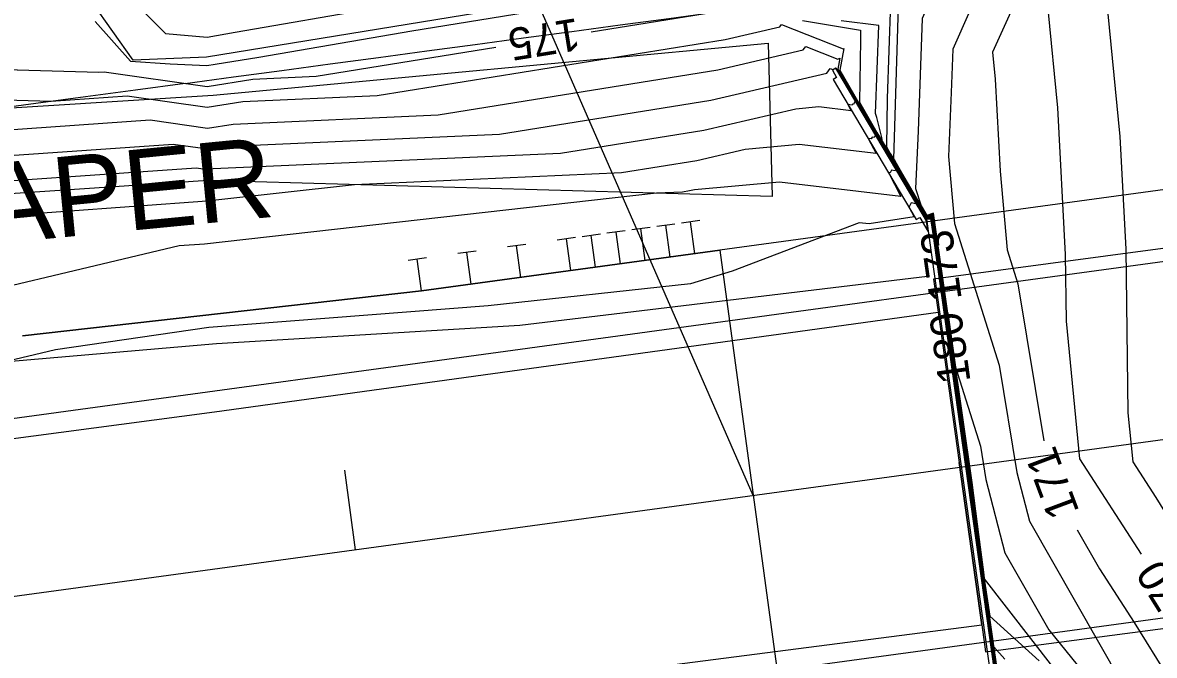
# Model space of a CAD drawing. Extents: x 2086416 to 2115205, y 575507 to 632762.
# Drawn here: x 2111995.5 to 2112066, y 581711.6 to 581751.1 of the extents above; entities that cross this region are included whole.
import ezdxf

# ---------------------------------------------------------------- set-up
doc = ezdxf.new("R2010")
doc.units = 0
for name, color, linetype in [('Default', 7, 'Continuous'), ('DTM Contours Major', 7, 'Continuous'), ('DTM Contours Major Text', 7, 'Continuous'), ('DTM Contours Minor', 7, 'Continuous'), ('DTM Contours Minor Text', 7, 'Continuous'), ('Exist Guardrail', 7, 'Continuous'), ('Exist Hydro Stream or Body of Water', 7, 'Continuous'), ('Exist Right of Way Line', 7, 'Continuous'), ('Exist Roads EOP', 7, 'Continuous'), ('Exist Structure Major Bridge WW', 7, 'Continuous'), ('Exist Structure Major Deck Tunnel Box Culvert', 7, 'Continuous'), ('Exist Vegetation Woods Line', 7, 'Continuous'), ('Prop Horizontal Alignment', 7, 'Continuous'), ('Prop Horizontal Alignment Station Label', 7, 'Continuous'), ('Prop Horizontal Alignment Tick Small', 7, 'Continuous'), ('Prop Roadway Bridge', 7, 'Continuous'), ('Prop SS Cut Line', 7, 'Continuous')]:
    doc.layers.add(name, color=color, linetype=linetype)

msp = doc.modelspace()

# ---------------------------------------------------------------- linework, layer by layer
at = {"layer": 'Default'}
for p, q in [((2111430.061, 581649.328), (2112312.029, 581769.688)), ((2111433.036, 581627.53), (2112315.004, 581747.89)), ((2112036.158, 581738.516), (2112035.023, 581738.361)), ((2112035.861, 581736.457), (2112035.591, 581738.439)), ((2112037.706, 581738.728), (2112036.571, 581738.573)), ((2112037.409, 581736.669), (2112037.139, 581738.65)), ((2112031.514, 581737.882), (2112030.379, 581737.728)), ((2112031.217, 581735.823), (2112030.946, 581737.805)), ((2112033.062, 581738.094), (2112031.927, 581737.939)), ((2112032.765, 581736.035), (2112032.494, 581738.016)), ((2112034.61, 581738.305), (2112033.475, 581738.15)), ((2112034.313, 581736.246), (2112034.042, 581738.228)), ((2112026.869, 581737.249), (2112025.734, 581737.094)), ((2112026.572, 581735.19), (2112026.302, 581737.171)), ((2112029.966, 581737.671), (2112028.831, 581737.516)), ((2112029.668, 581735.612), (2112029.398, 581737.594)), ((2112020.677, 581736.404), (2112019.542, 581736.249)), ((2112020.38, 581734.345), (2112020.109, 581736.326)), ((2112038.957, 581736.88), (2112020.38, 581734.345)), ((2112020.38, 581734.345), (2112038.957, 581736.88)), ((2112023.773, 581736.826), (2112022.638, 581736.671)), ((2112023.476, 581734.767), (2112023.205, 581736.749)), ((2111995.53, 581731.542), (2112020.38, 581734.345)), ((2112020.38, 581734.345), (2111995.53, 581731.542))]:
    msp.add_line(p, q, dxfattribs=at)
at = {"layer": 'DTM Contours Major'}
for points in [[(2112093.804, 581744.757), (2112090.042, 581754.014), (2112084.44, 581764.888), (2112082.003, 581767.922), (2112071.785, 581774.964), (2112068.207, 581770.089), (2112066.687, 581768.005), (2112059.39, 581751.908), (2112059.991, 581745.748), (2112060.467, 581736.615), (2112060.524, 581732.474), (2112061.368, 581723.884), (2112065.2, 581717.945)], [(2112030.936, 581750.481), (2112039.721, 581751.9)], [(2112044.102, 581751.189), (2112047.713, 581750.589), (2112047.719, 581749.965), (2112047.666, 581746.104), (2112048.736, 581744.226), (2112050.093, 581742.006), (2112051.838, 581738.979), (2112051.843, 581739), (2112051.898, 581739.008), (2112052.22, 581739.112), (2112054.232, 581725.192), (2112054.991, 581719.398), (2112055.55, 581715.417), (2112056.626, 581707.916)], [(2111925.764, 581740.81), (2111939.964, 581741.818), (2111942.786, 581742.121), (2111957.222, 581743.139), (2111973.757, 581745.604), (2111976.305, 581745.781), (2111990.111, 581748.256), (2112000.275, 581747.973), (2112000.618, 581747.997), (2112007.016, 581747.085), (2112009.871, 581747.542), (2112013.821, 581747.717), (2112025.013, 581749.525)], [(2112052.875, 581733.796), (2112052.825, 581734.177), (2112052.137, 581738.939), (2112052.027, 581738.903), (2112051.845, 581738.878), (2112051.827, 581738.808), (2112051.245, 581739.819), (2112048.65, 581744.064), (2112048.579, 581743.898), (2112048.439, 581743.929), (2112048.382, 581743.814), (2112048.199, 581743.844), (2112048.686, 581742.903), (2112043.902, 581743.464), (2112040.534, 581743.16), (2112037.519, 581742.461), (2112032.824, 581741.703), (2112016.209, 581740.966), (2112007.008, 581739.932), (2111993.349, 581738.951), (2111987.178, 581737.484), (2111979.955, 581737.182), (2111962.616, 581735.882)], [(2111984.298, 581691.845), (2111991.51, 581693.189), (2111995.196, 581693.902), (2112011.564, 581696.953), (2112016.807, 581698.169), (2112041.287, 581700.92), (2112041.717, 581701.015), (2112046.837, 581701.591), (2112048.852, 581702.413), (2112054.344, 581703.379), (2112054.34, 581703.36), (2112054.13, 581701.681), (2112054.225, 581701.662), (2112054.385, 581701.619), (2112055.986, 581706.942), (2112056.231, 581707.78), (2112056.23, 581707.966), (2112056.399, 581707.991), (2112056.489, 581708.003), (2112056.386, 581708.74), (2112056.033, 581711.197), (2112053.695, 581727.852)]]:
    msp.add_lwpolyline(points, dxfattribs=at)
at = {"layer": 'DTM Contours Minor'}
for points in [[(2112088.832, 581814.717), (2112079.117, 581800.733), (2112078.139, 581799.131), (2112071.052, 581784.529), (2112066.895, 581774.978), (2112066.081, 581772.081), (2112065.416, 581771.202), (2112065.876, 581771.198), (2112064.244, 581767.513), (2112055.948, 581749.212), (2112056.111, 581747.536), (2112056.41, 581741.807), (2112056.854, 581736.905), (2112057.524, 581734.784), (2112059.14, 581725.01)], [(2112066.275, 581795.739), (2112047.998, 581793.548), (2112061.063, 581775.542), (2112061.722, 581774.652), (2112054.081, 581764.549), (2112060.152, 581764.507), (2112053.463, 581749.403), (2112053.368, 581746.704), (2112053.198, 581742.712), (2112053.575, 581738.546), (2112056.358, 581729.732), (2112057.466, 581723.036), (2112058.244, 581720.01), (2112063.976, 581709.948), (2112064.076, 581709.792), (2112064.176, 581709.631), (2112064.52, 581708.577), (2112068.431, 581698.956)], [(2111990.873, 581783.424), (2111997.45, 581781.941), (2111996.551, 581772.464), (2111996.221, 581769.419), (2112001.249, 581756.244), (2112002.407, 581752.402), (2112004.434, 581750.394), (2112007.018, 581750.164), (2112008.767, 581750.469), (2112026.584, 581753.57), (2112026.238, 581757.953), (2112041.947, 581766.094), (2112043.662, 581758.151), (2112045.558, 581757.878), (2112054.428, 581757.817), (2112051.55, 581751.319), (2112051.304, 581744.309), (2112051.151, 581740.719), (2112051.49, 581739.658), (2112051.842, 581739.048), (2112051.842, 581739.049), (2112051.846, 581739.05), (2112052.253, 581739.181), (2112052.291, 581738.921)], [(2112090.836, 581746.669), (2112087.884, 581753.931), (2112083.489, 581762.461), (2112080.052, 581766.74), (2112072.781, 581771.751), (2112070.235, 581768.282), (2112067.06, 581763.928), (2112062.833, 581754.603), (2112063.87, 581743.961), (2112064.236, 581736.951), (2112064.376, 581726.748), (2112064.675, 581723.707), (2112066.115, 581721.476), (2112068.073, 581718.32), (2112071.422, 581714.164), (2112071.682, 581713.878)], [(2112000.048, 581751.131), (2112002.239, 581748.66), (2112004.722, 581748.487), (2112006.997, 581748.388), (2112007.528, 581748.479), (2112010.249, 581748.915), (2112019.764, 581750.541), (2112039.664, 581753.78)], [(2112049.596, 581752.312), (2112049.386, 581746.335), (2112049.345, 581743.317), (2112049.573, 581742.917), (2112049.862, 581742.443), (2112051.84, 581739.014), (2112051.842, 581739.025), (2112051.872, 581739.029), (2112052.236, 581739.147), (2112054.513, 581723.395), (2112055.372, 581716.839), (2112055.453, 581716.261), (2112055.766, 581714.082), (2112058.851, 581711.313)], [(2111989.42, 581746.388), (2111997.31, 581746.168), (2112002.05, 581746.498), (2112007.032, 581745.788), (2112009.255, 581746.143), (2112017.621, 581746.514), (2112039.28, 581750.013), (2112042.69, 581750.803), (2112042.793, 581750.943), (2112046.635, 581749.422), (2112046.673, 581749.442), (2112046.438, 581748.1), (2112047.898, 581745.536), (2112050.323, 581741.569), (2112051.835, 581738.945), (2112051.843, 581738.976), (2112051.923, 581738.987), (2112052.203, 581739.077), (2112053.951, 581726.989), (2112054.61, 581721.958), (2112055.647, 581714.573), (2112056.578, 581708.081)], [(2111994.345, 581744.364), (2112003.483, 581744.998), (2112007.047, 581744.49), (2112008.638, 581744.744), (2112021.422, 581745.311), (2112038.84, 581748.125), (2112044.156, 581749.357), (2112044.316, 581749.575), (2112046.314, 581748.784), (2112046.434, 581748.846), (2112046.313, 581748.159), (2112047.061, 581746.845), (2112050.553, 581741.131), (2112051.833, 581738.911), (2112051.844, 581738.951), (2112051.949, 581738.966), (2112052.187, 581739.043), (2112053.669, 581728.786), (2112054.229, 581724.517), (2112055.743, 581713.729), (2112056.53, 581708.246)], [(2111991.38, 581742.559), (2112004.916, 581743.499), (2112007.063, 581743.193), (2112008.021, 581743.346), (2112025.223, 581744.108), (2112038.399, 581746.237), (2112045.621, 581747.911), (2112045.839, 581748.207), (2112045.994, 581748.146), (2112046.194, 581748.25), (2112046.188, 581748.217), (2112046.224, 581748.155), (2112050.784, 581740.694), (2112051.831, 581738.876), (2112051.844, 581738.927), (2112051.975, 581738.945), (2112052.17, 581739.008), (2112053.388, 581730.583), (2112053.847, 581727.076), (2112055.84, 581712.885), (2112056.482, 581708.41)], [(2112056.434, 581708.575), (2112055.937, 581712.041), (2112053.466, 581729.636), (2112053.107, 581732.38), (2112052.154, 581738.974), (2112052.001, 581738.924), (2112051.845, 581738.902), (2112051.829, 581738.842), (2112051.014, 581740.256), (2112047.384, 581746.196), (2112047.286, 581745.963), (2112047.223, 581745.977), (2112047.197, 581745.925), (2112046.937, 581745.968), (2112047.143, 581745.571), (2112045.122, 581745.808), (2112043.698, 581745.679), (2112037.959, 581744.349), (2112029.023, 581742.905), (2112007.404, 581741.947), (2112007.078, 581741.895), (2112006.348, 581741.999), (2111988.896, 581740.788)], [(2112056.13, 581710.354), (2112052.704, 581734.754), (2112052.544, 581735.974), (2112052.121, 581738.904), (2112052.053, 581738.882), (2112051.845, 581738.853), (2112051.825, 581738.774), (2112051.475, 581739.381), (2112049.915, 581741.933), (2112049.873, 581741.834), (2112049.655, 581741.881), (2112049.566, 581741.702), (2112049.461, 581741.72), (2112050.228, 581740.236), (2112042.683, 581741.121), (2112037.37, 581740.641), (2112037.078, 581740.573), (2112036.624, 581740.5), (2112035.018, 581740.429), (2112006.848, 581737.262), (2112005.287, 581737.15), (2111987.473, 581732.914)], [(2112056.227, 581709.51), (2112052.323, 581737.313), (2112052.263, 581737.771), (2112052.104, 581738.87), (2112052.078, 581738.862), (2112051.846, 581738.829), (2112051.823, 581738.739), (2112051.705, 581738.944), (2112051.18, 581739.802), (2112051.166, 581739.769), (2112050.871, 581739.833), (2112050.751, 581739.591), (2112050.722, 581739.595), (2112051.052, 581738.959), (2112048.264, 581738.519), (2112047.644, 581738.592), (2112039.718, 581735.589), (2112037.125, 581734.798), (2112024.517, 581733.414), (2112007.137, 581732.061), (2111997.584, 581730.679), (2111987.768, 581728.345)], [(2112053.149, 581732.983), (2112053.637, 581729.605), (2112055.192, 581724.68), (2112055.536, 581722.602), (2112056.71, 581718.039), (2112059.448, 581713.234), (2112063.337, 581708.445), (2112065.522, 581703.069), (2112063.58, 581699.407), (2112062.948, 581692.044), (2112060.031, 581679.765), (2112054.922, 581680.384), (2112054.842, 581673.735)], [(2112061.214, 581719.459), (2112062.599, 581717.028), (2112064.756, 581713.686), (2112066.895, 581710.238), (2112070.142, 581700.284), (2112072.84, 581697.236), (2112070.631, 581692.11), (2112066.05, 581673.082), (2112062.824, 581653.079), (2112059.859, 581649.8), (2112053.487, 581643.439), (2112049.372, 581635.991)]]:
    msp.add_lwpolyline(points, dxfattribs=at)
at = {"layer": 'Exist Guardrail'}
msp.add_lwpolyline([(2111568.013, 581669.491), (2111592.858, 581673.514), (2111642.147, 581682.489), (2111666.782, 581686.916), (2111710.045, 581692.984), (2111759.576, 581699.833), (2111809.182, 581706.828), (2111858.616, 581713.631), (2111908.173, 581720.547), (2111932.899, 581724.161), (2111951.42, 581726.236), (2112007.614, 581731.068), (2112026.509, 581732.213), (2112051.896, 581735.258)], dxfattribs=at)
at = {"layer": 'Exist Hydro Stream or Body of Water'}
msp.add_lwpolyline([(2112059.937, 581700.976), (2112062.587, 581707.218), (2112055.437, 581716.404), (2112054.668, 581722.407), (2112052.263, 581739.202), (2112051.842, 581739.053), (2112049.8, 581742.562), (2112050.106, 581752.765), (2112039.24, 581754.189), (2112006.974, 581748.916), (2112002.418, 581748.716), (2111999.873, 581752.286), (2111991.633, 581772.37), (2111979.181, 581775.683), (2111967.531, 581787.222), (2111962.273, 581798.517)], dxfattribs=at)
at = {"layer": 'Exist Right of Way Line'}
for centre, radius, start, end in [((2100483.795, 667614.96), 86637.248, 277.64238767, 277.77100557), ((2119136.647, 528602.897), 53620.666, 97.6423877, 97.8562149), ((2100483.795, 667614.96), 86697.248, 277.64238767, 277.77100557)]:
    msp.add_arc(centre, radius, start, end, dxfattribs=at)
at = {"layer": 'Exist Roads EOP'}
for points in [[(2111568.946, 581657.382), (2111567.482, 581667.278), (2111614.169, 581673.234), (2111663.501, 581679.942), (2111712.967, 581686.457), (2111762.009, 581693.34), (2111810.989, 581700.16), (2111860.082, 581706.99), (2111909.436, 581713.775), (2111958.293, 581720.29), (2112007.473, 581726.809), (2112052.556, 581733.019), (2112053.866, 581723.651)], [(2111568.946, 581657.382), (2111567.482, 581667.278), (2111614.169, 581673.234), (2111663.501, 581679.942), (2111712.967, 581686.457), (2111762.009, 581693.34), (2111810.989, 581700.16), (2111860.082, 581706.99), (2111909.436, 581713.775), (2111958.293, 581720.29), (2112007.473, 581726.809), (2112052.556, 581733.019), (2112053.866, 581723.651)], [(2111568.946, 581657.382), (2111570.384, 581647.665), (2111616.941, 581653.786), (2111666.479, 581660.703), (2111715.395, 581667.634), (2111764.576, 581674.503), (2111813.386, 581681.192), (2111862.599, 581687.866), (2111911.635, 581694.622), (2111960.562, 581701.229), (2112009.92, 581707.698), (2112055.279, 581713.547), (2112053.866, 581723.651)]]:
    msp.add_lwpolyline(points, dxfattribs=at)
at = {"layer": 'Exist Structure Major Bridge WW'}
for points in [[(2112051.912, 581738.081), (2112051.822, 581738.722), (2112051.614, 581739.073), (2112046.182, 581748.22), (2112045.967, 581748.092), (2112046.229, 581747.65), (2112046.014, 581747.523), (2112051.194, 581738.801), (2112051.408, 581738.929), (2112051.912, 581738.081)], [(2112056.418, 581708.08), (2112056.17, 581708.045), (2112051.846, 581738.814), (2112052.094, 581738.849), (2112056.418, 581708.08)]]:
    msp.add_lwpolyline(points, dxfattribs=at)
at = {"layer": 'Exist Structure Major Deck Tunnel Box Culvert'}
msp.add_lwpolyline([(2112052.266, 581735.09), (2112052.556, 581733.019), (2112053.866, 581723.651), (2112055.279, 581713.547), (2112055.513, 581711.876), (2112073.348, 581714.22), (2112090.179, 581716.432), (2112107.623, 581718.725), (2112107.323, 581720.971), (2112106.042, 581730.564), (2112104.785, 581739.983), (2112104.506, 581742.07), (2112086.984, 581739.728), (2112070.121, 581737.475), (2112052.266, 581735.09)], dxfattribs=at)
at = {"layer": 'Exist Vegetation Woods Line'}
for points in [[(2111543.005, 581784.097), (2111565.769, 581734.523), (2111587.195, 581707.454), (2111708.986, 581713.776), (2111811.987, 581727.732), (2111909.413, 581740.402), (2112007.408, 581746.548), (2112041.962, 581749.787), (2112042.216, 581740.223)], [(2112042.216, 581740.223), (2112007.086, 581741.227), (2111957.142, 581737.865), (2111908.66, 581731.855), (2111808.648, 581718.236), (2111760.407, 581712.702), (2111710.337, 581706.767), (2111661.65, 581697.223), (2111616.664, 581692.442), (2111575.004, 581689.288), (2111546.91, 581687.078), (2111515.04, 581695.859), (2111502.165, 581702.852), (2111491.109, 581719.623), (2111479.278, 581746.112)]]:
    msp.add_lwpolyline(points, dxfattribs=at)
at = {"layer": 'Prop Horizontal Alignment'}
msp.add_line((2111431.548, 581638.429), (2112404.465, 581771.2), dxfattribs=at)
at = {"layer": 'Prop Horizontal Alignment Station Label'}
msp.add_line((2112041.042, 581721.605), (2111981.252, 581858.374), dxfattribs=at)
at = {"layer": 'Prop Horizontal Alignment Tick Small'}
msp.add_line((2112016.271, 581718.224), (2112015.595, 581723.178), dxfattribs=at)
at = {"layer": 'Prop Roadway Bridge'}
for p, q in [((2112118.223, 581747.697), (2112038.957, 581736.88)), ((2112038.957, 581736.88), (2112043.126, 581706.33))]:
    msp.add_line(p, q, dxfattribs=at)
at = {"layer": 'Prop SS Cut Line'}
for p, q in [((2112048.87, 581750.879), (2112046.524, 581751.179)), ((2112048.663, 581745.399), (2112048.87, 581750.879)), ((2112051.842, 581739.025), (2112049.148, 581743.399)), ((2112052.236, 581739.147), (2112051.842, 581739.025)), ((2112056.028, 581712.178), (2112052.236, 581739.147)), ((2112056.714, 581711.417), (2112056.028, 581712.178))]:
    msp.add_line(p, q, dxfattribs=at)
msp.add_arc((2112014.711, 581736.119), 35.198, 11.93742, 15.28725, dxfattribs=at)

# ---------------------------------------------------------------- texts
at = {"layer": 'Default'}
msp.add_text('50:1 TAPER', height=5, rotation=5.54573, dxfattribs=at).set_placement((2111974.326, 581735.387))
at = {"layer": 'DTM Contours Major Text'}
for s, rotation, p in [('175', 189.17611, (2112030.062, 581751.353)), ('180', 97.8505, (2112054.579, 581728.705)), ('170', 121.88866, (2112068.839, 581713.996))]:
    msp.add_text(s, height=2, rotation=rotation, dxfattribs=at).set_placement(p)
at = {"layer": 'DTM Contours Minor Text'}
for s, rotation, p in [('173', 98.22491, (2112054.035, 581733.843)), ('171', 110.48716, (2112061.368, 581720.611))]:
    msp.add_text(s, height=2, rotation=rotation, dxfattribs=at).set_placement(p)

doc.saveas('drawing.dxf')
